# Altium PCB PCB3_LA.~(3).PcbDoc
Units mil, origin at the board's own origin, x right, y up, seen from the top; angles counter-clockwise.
Board outline 1968 x 1968 mil, 4 copper layers (Top Layer, Internal Plane 1, Internal Plane 2, Bottom Layer), stack 18.2 mil thick; 12 components, 11 nets, 38 pads, 0 vias.
Unrouted connection lines stored in the file: 24.
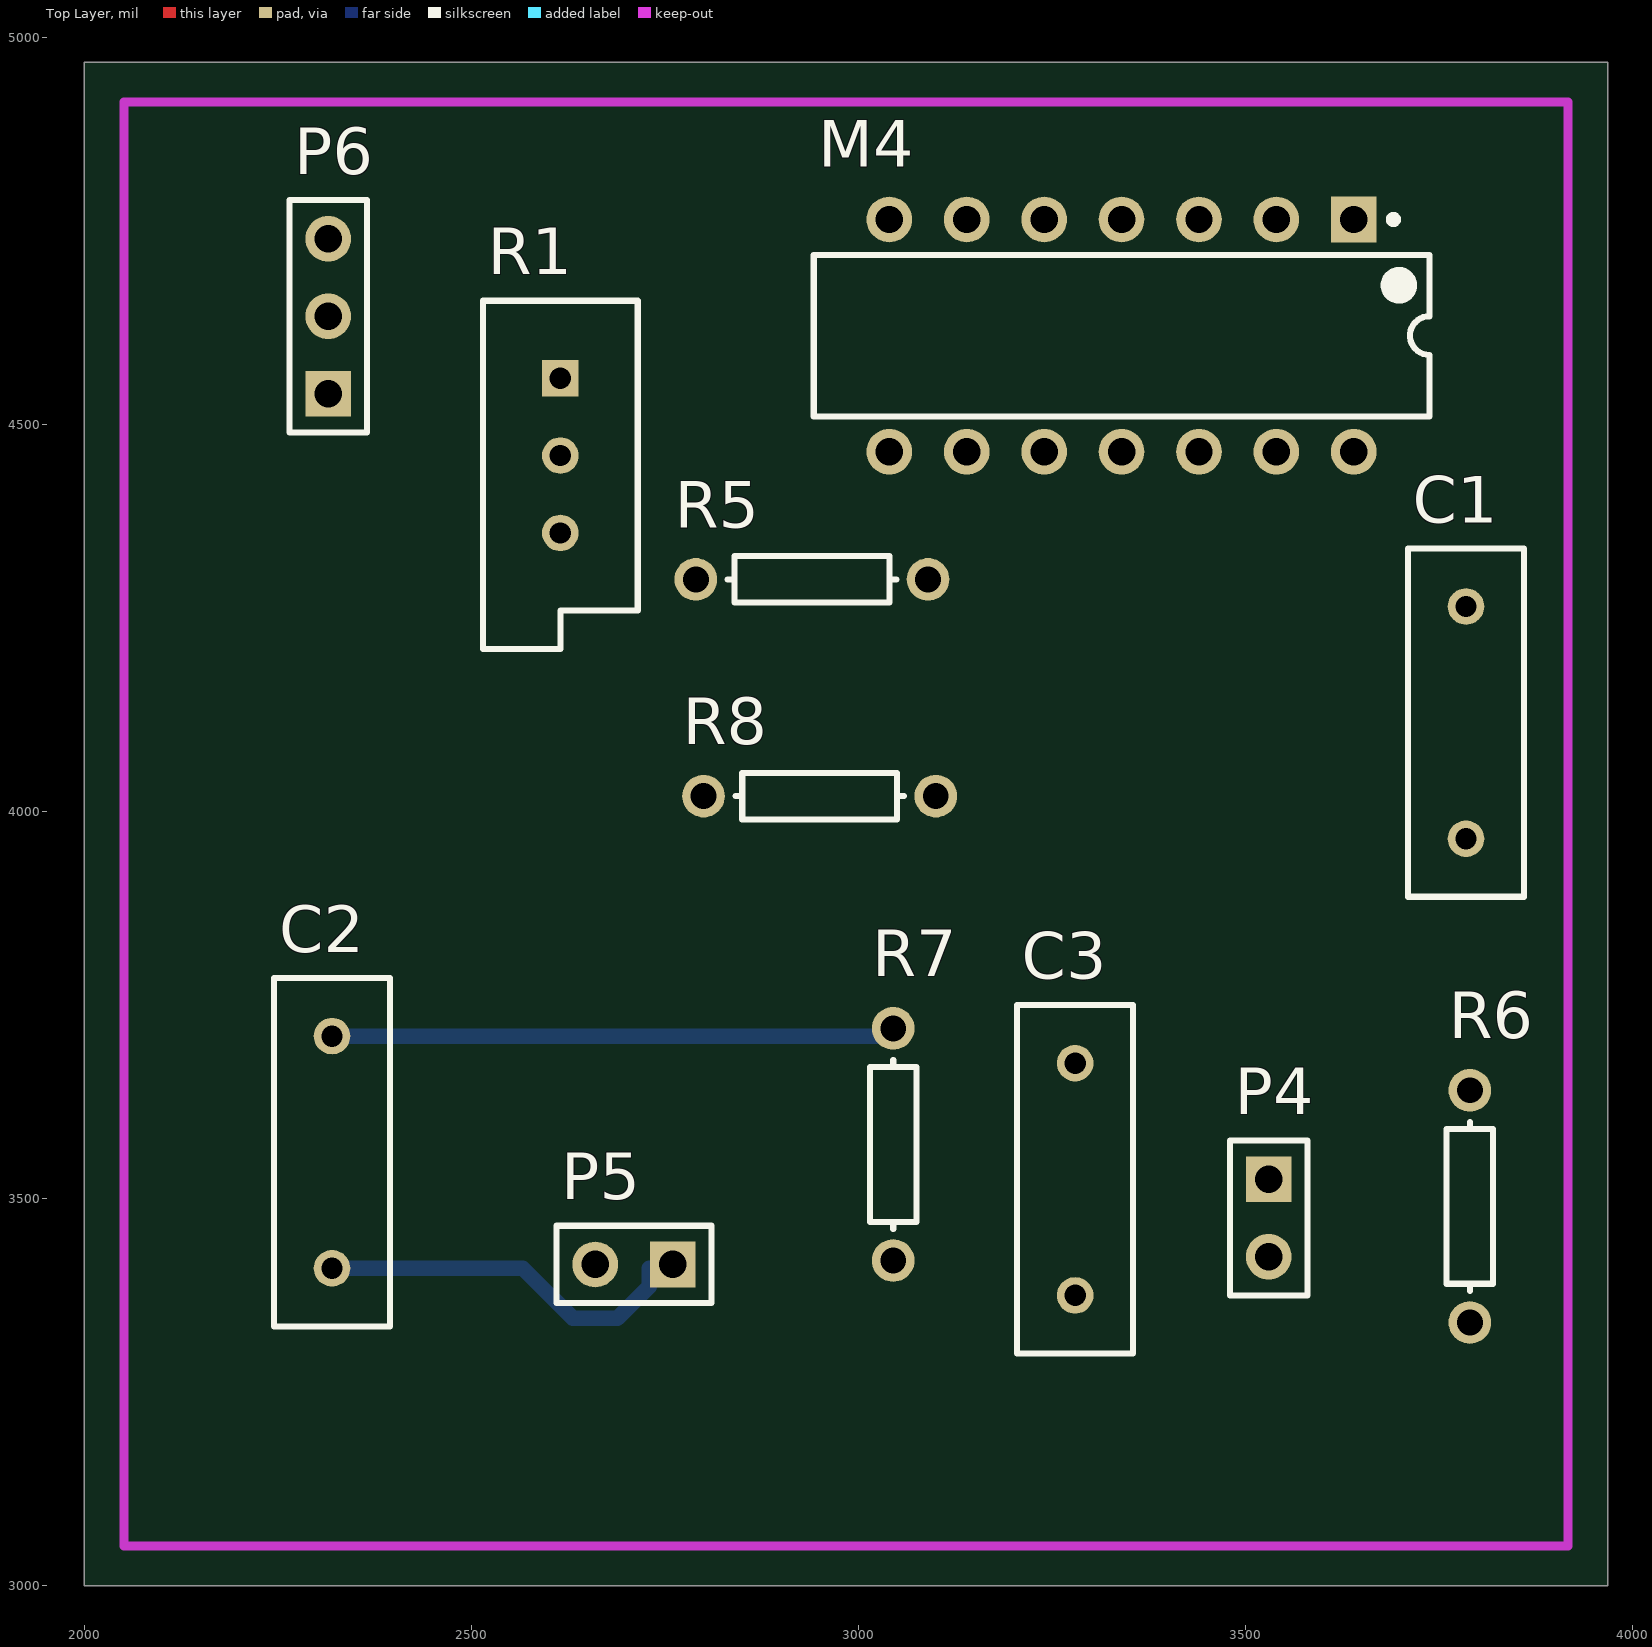
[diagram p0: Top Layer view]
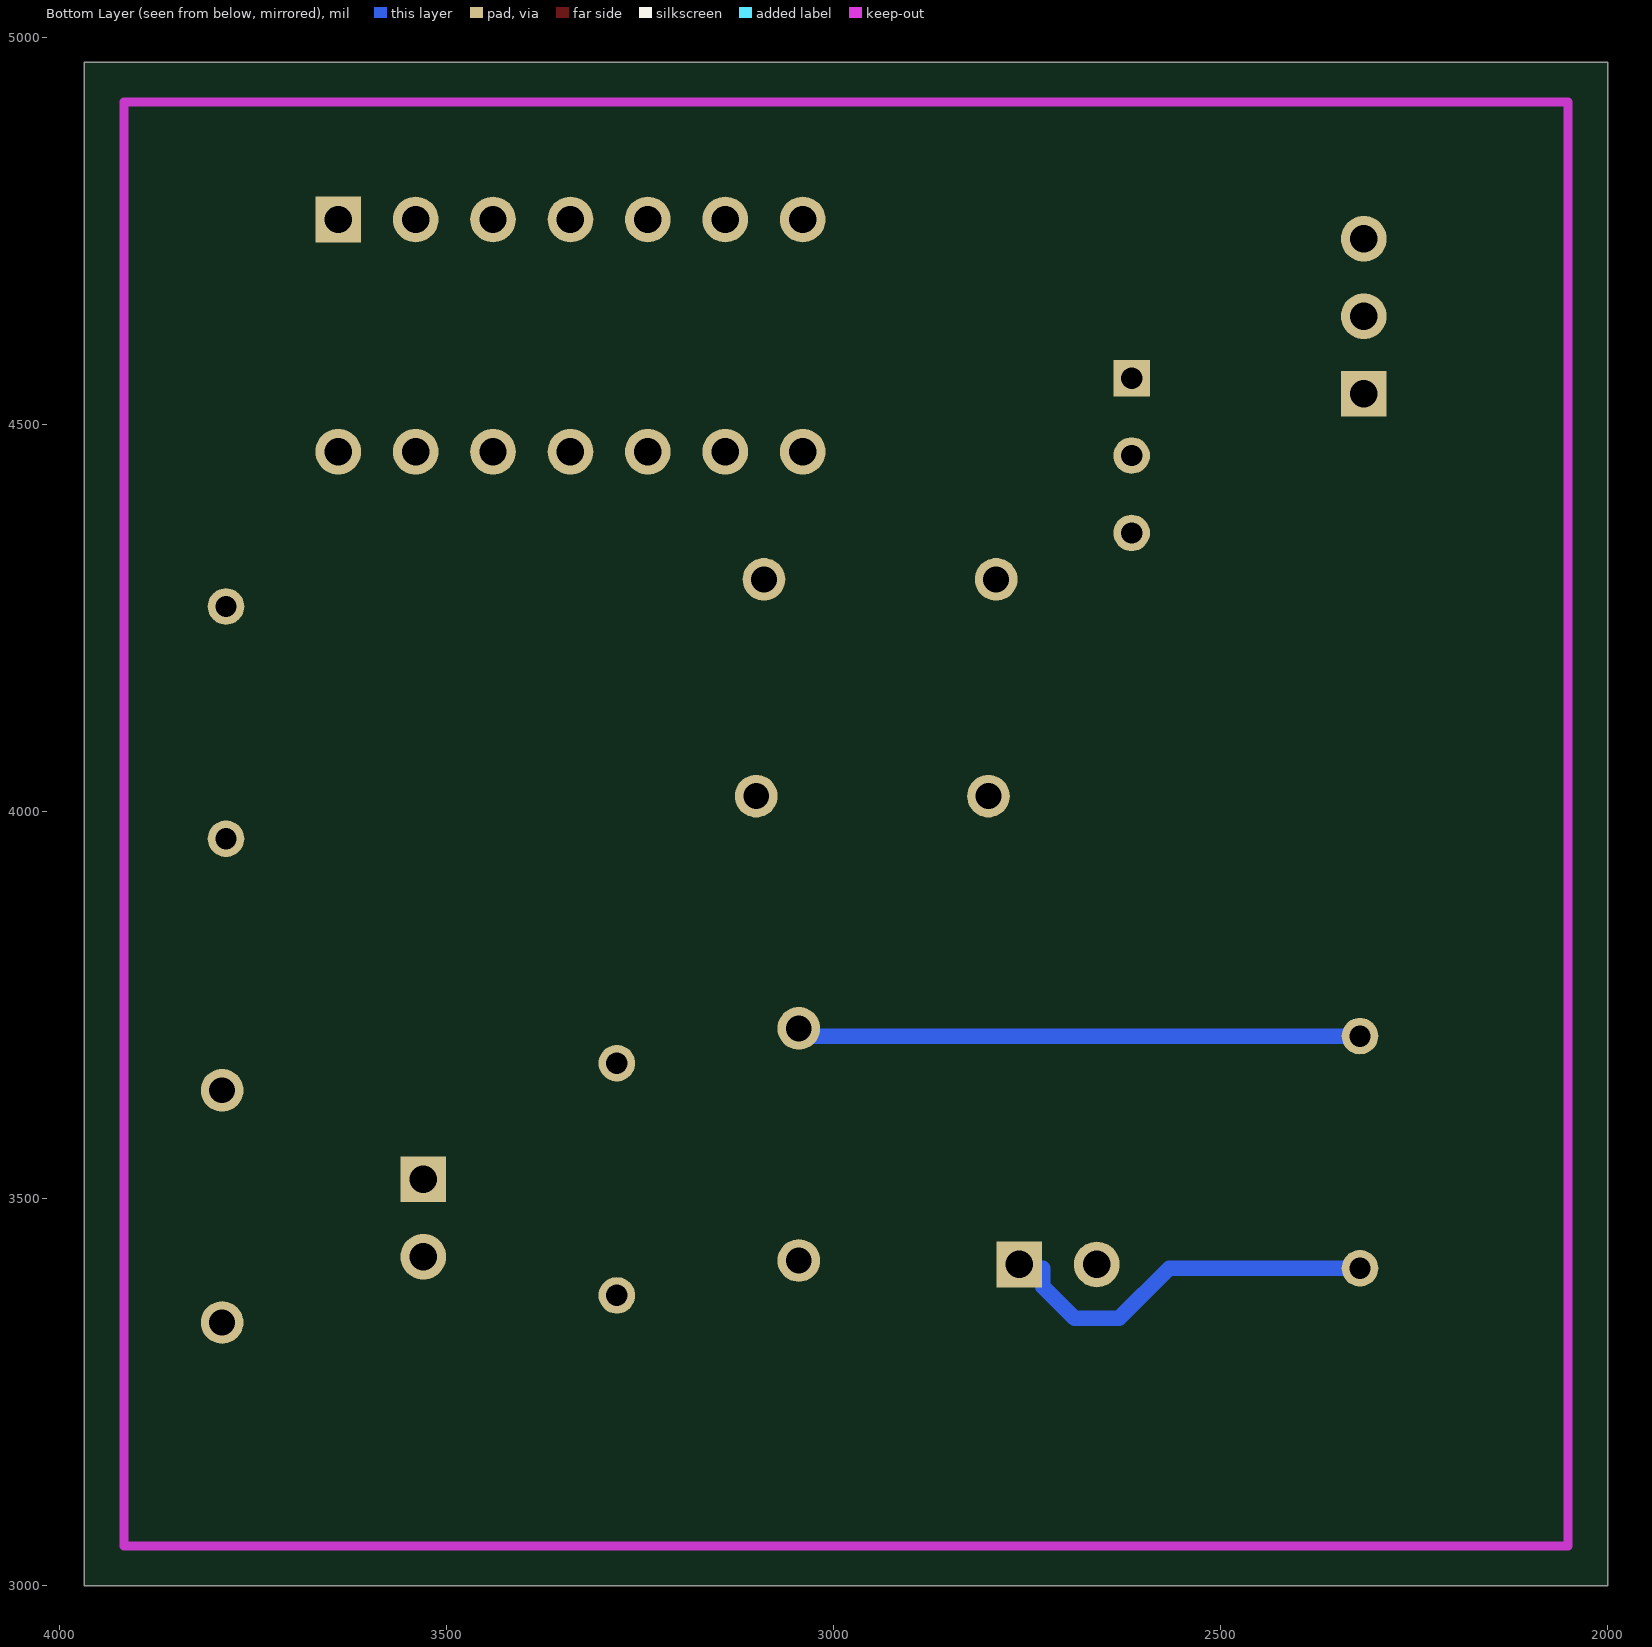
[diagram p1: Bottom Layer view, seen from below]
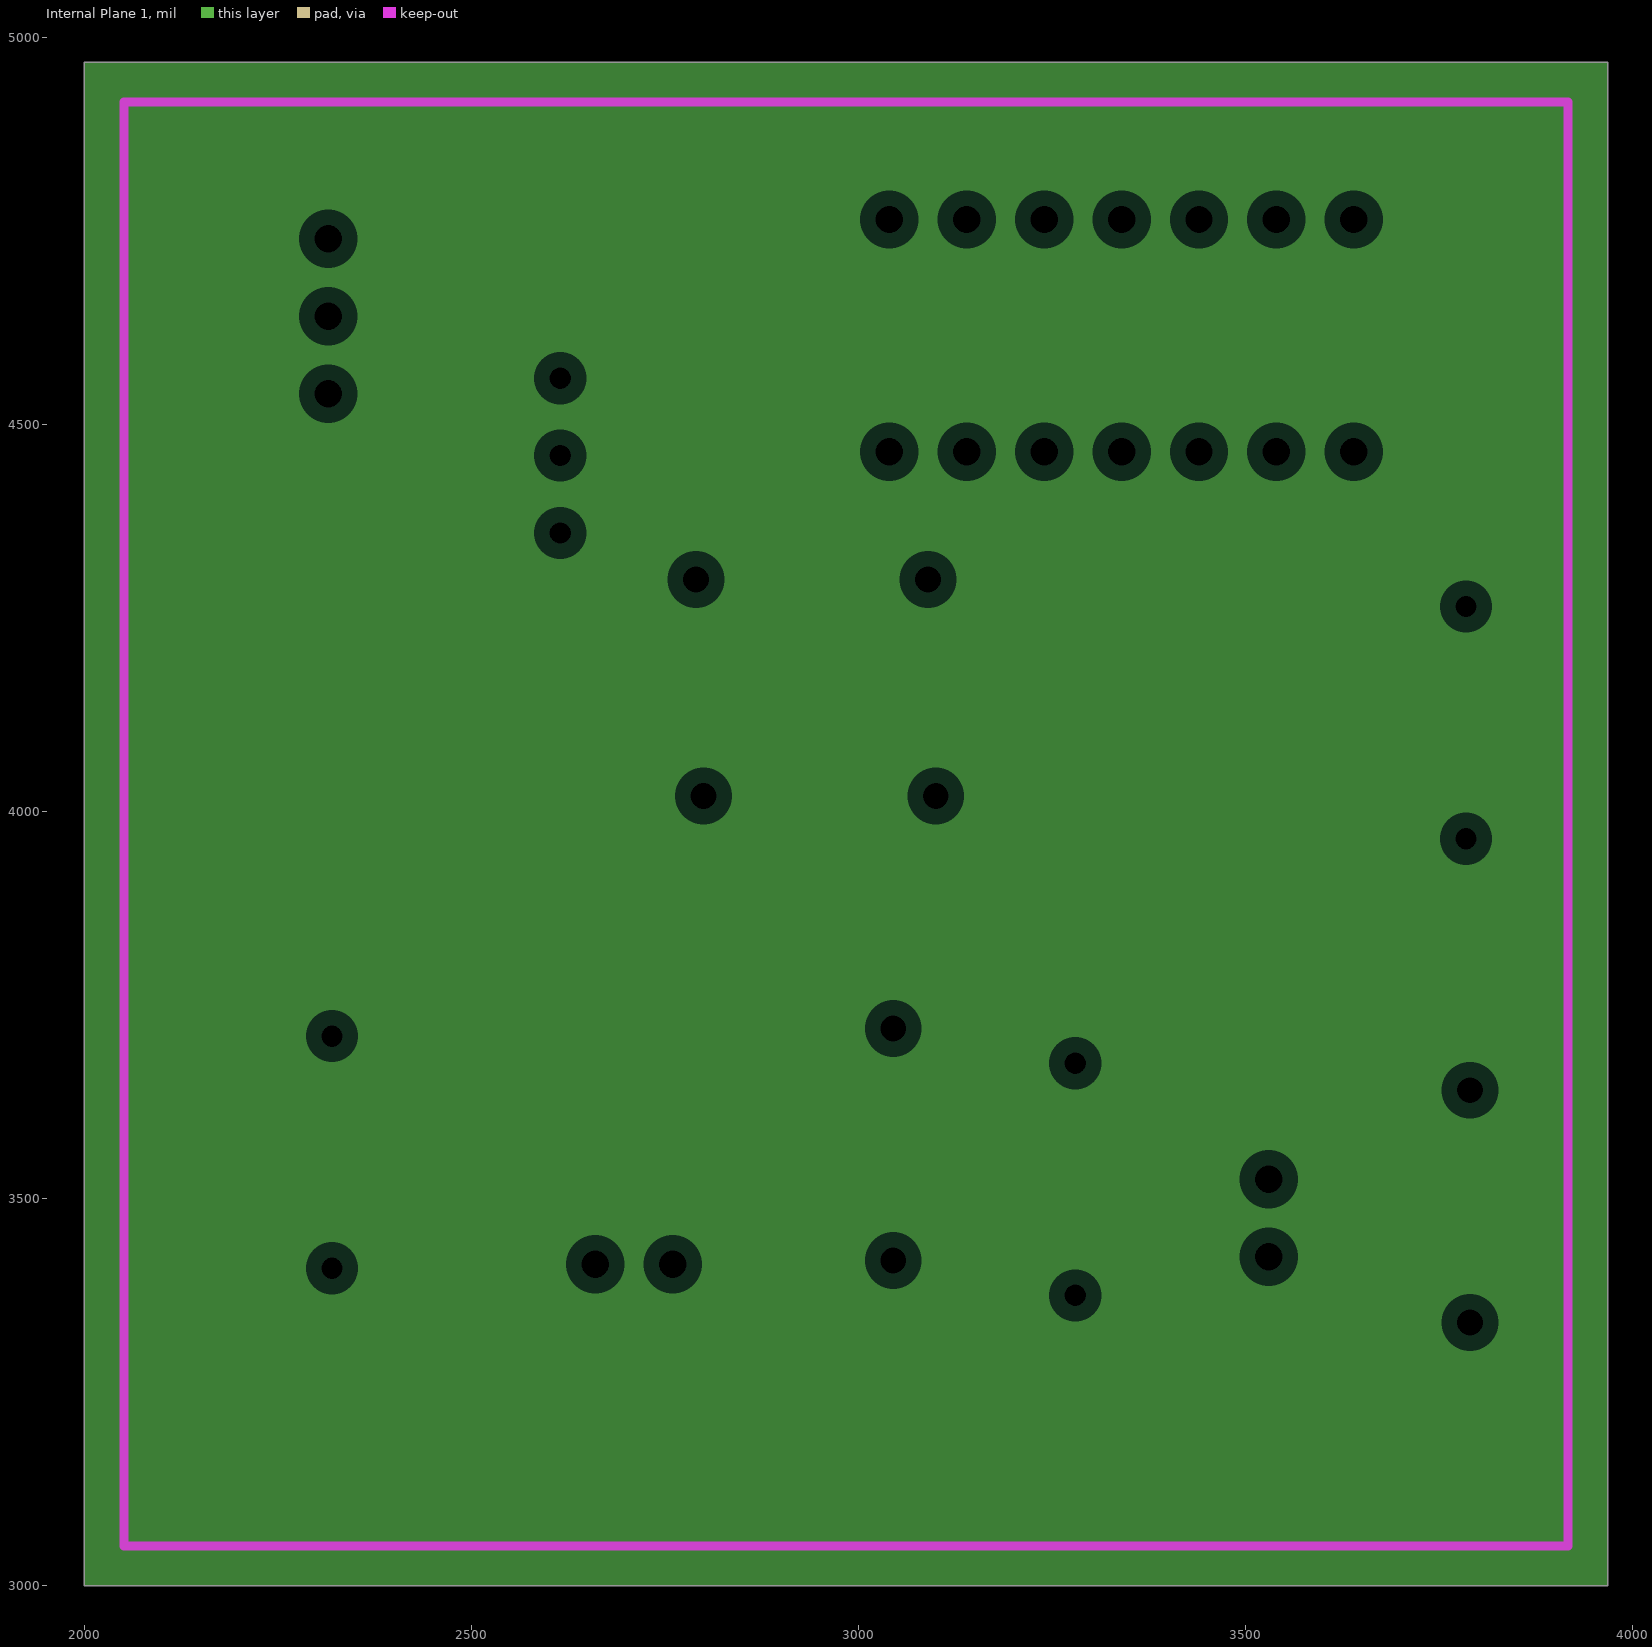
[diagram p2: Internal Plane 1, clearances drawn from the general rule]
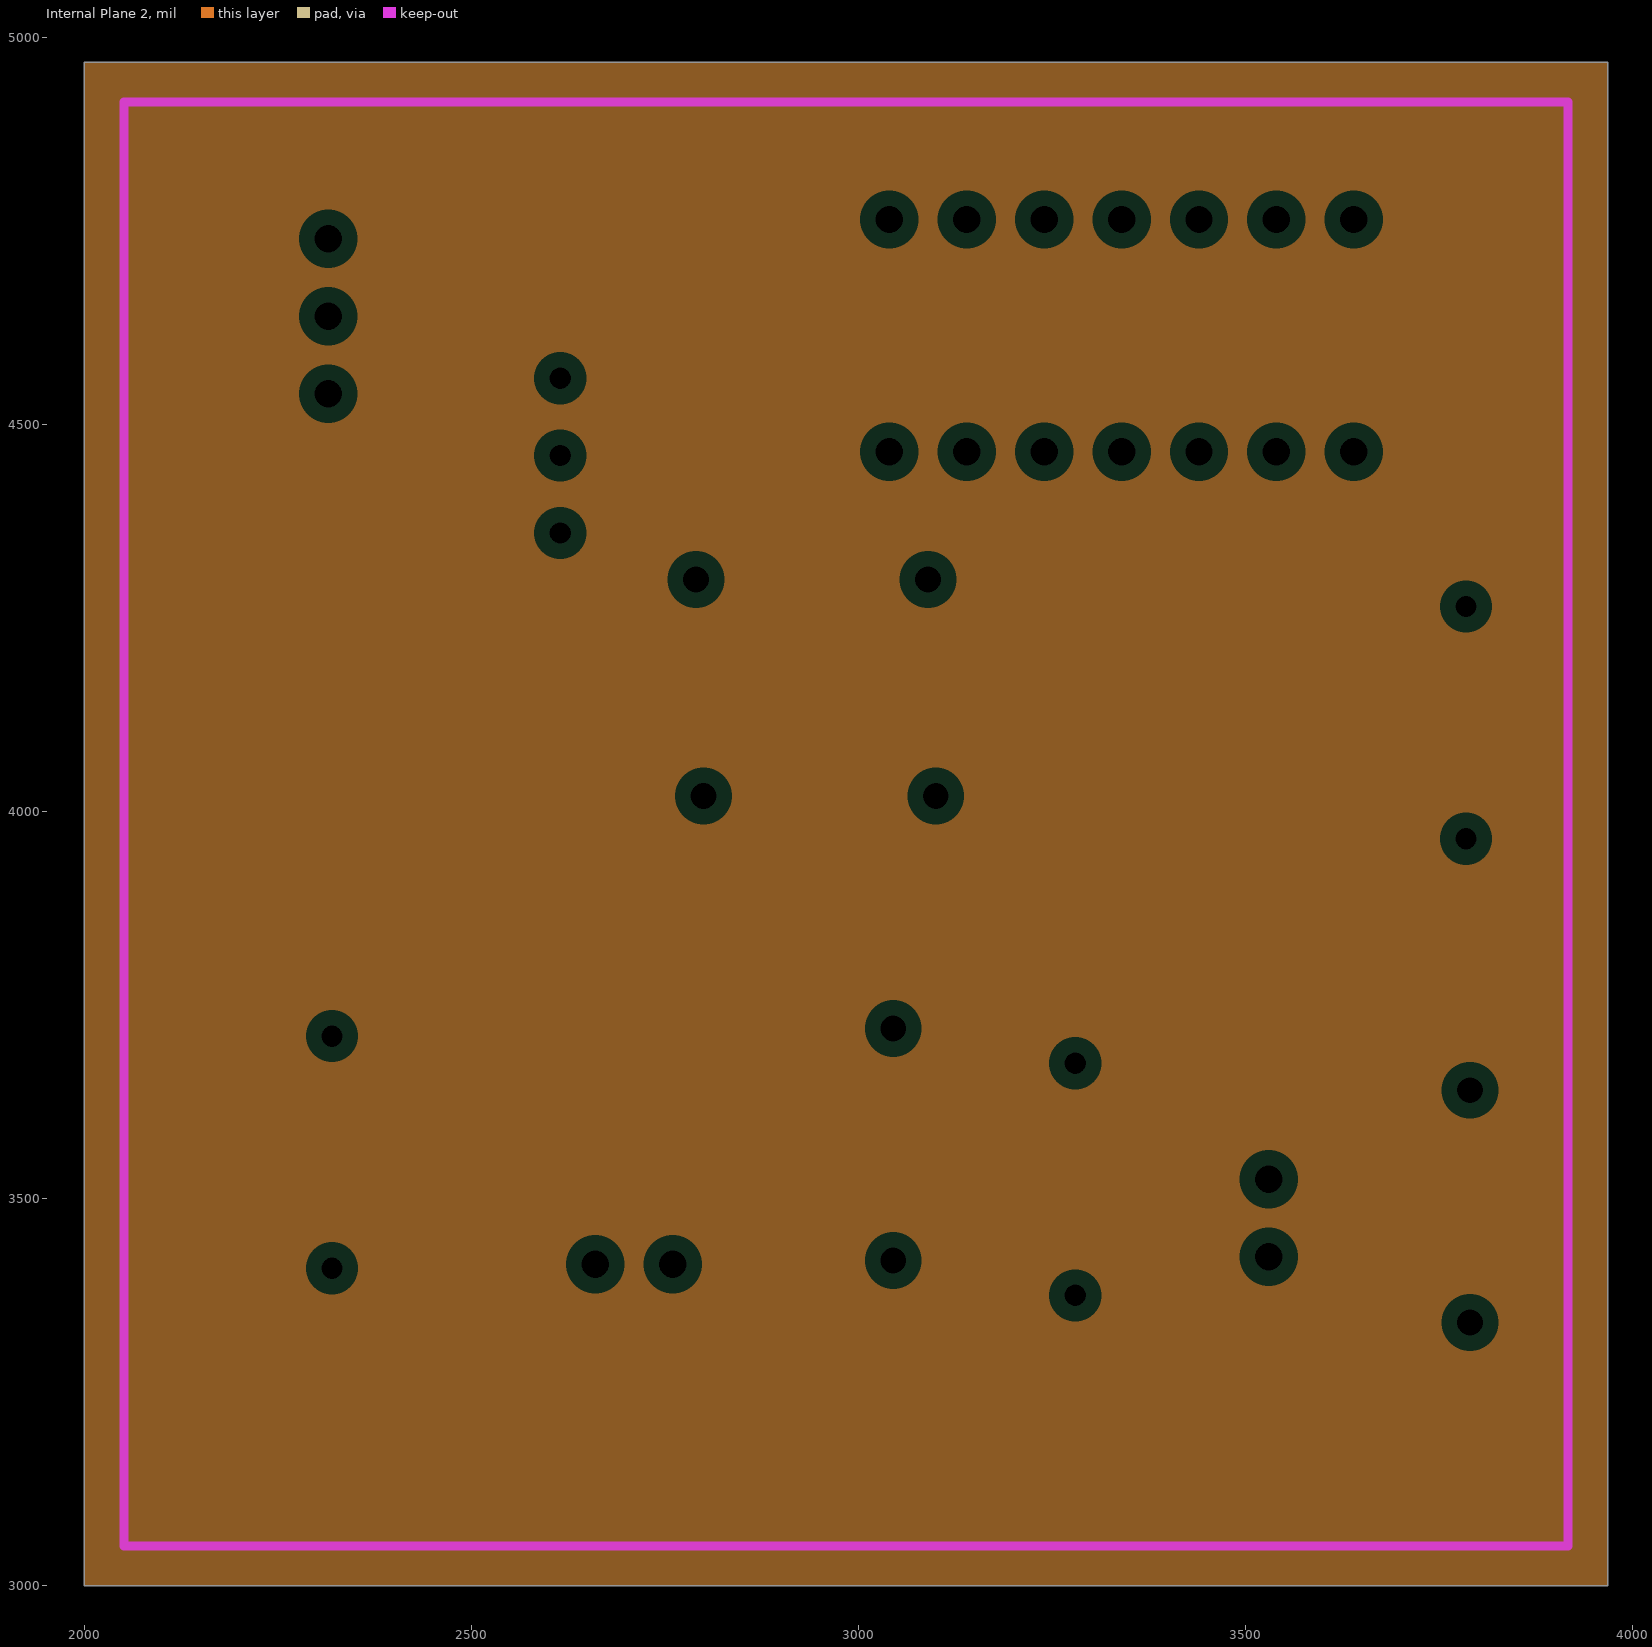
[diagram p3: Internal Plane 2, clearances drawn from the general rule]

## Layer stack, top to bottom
Top Solder: solder mask 0.4, Solder Resist, Dk 3.5
Top Layer: signal copper 1.4
Internal Plane 1: plane copper 1.4
Internal Plane 2: plane copper 1.4
Dielectric 1: dielectric 12.6, FR-4, Dk 4.8
Bottom Layer: signal copper 1.4
Bottom Solder: solder mask 0.4, Solder Resist, Dk 3.5

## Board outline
2000,3000 3968,3000 3968,4968 2000,4968

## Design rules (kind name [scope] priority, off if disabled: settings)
Clearance [All] p1: gap=30
PlaneClearance [All] p1: clearance=20
PlaneConnect [All] p1: planeconnectstyle=Relief reliefexpansion=20 reliefentries=4 reliefconductorwidth=10 reliefairgap=10
PolygonConnect [All] p1: connectstyle=Relief reliefconductorwidth=10 reliefentries=4 polygonreliefangle="90 Angle" airgapwidth=10
RoutingVias [All] p1: holewidth=32 width=62 viastyle="Through Hole" minholewidth=28 minwidth=50 maxholewidth=28 maxwidth=50
SolderMaskExpansion [All] p1: expansion=4
Width [All] p1: maxlimit=20 minlimit=20 preferedwidth=20
28 further rules are at their usual default settings.

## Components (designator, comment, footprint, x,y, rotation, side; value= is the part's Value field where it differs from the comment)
C1 "Cap" RAD-0.3 3785,4115 r90 top
C2 "Cap" RAD-0.3 2320,3560 r90 top
C3 "Cap" RAD-0.3 3280,3525 r270 top
M4 "ALD1106" DIP-14 3340,4615 r270 top
P4 "Header 2" HDR1X2 3530,3525 r270 top
P5 "Header 2" HDR1X2 2760,3415 r180 top
P6 "Header 3" HDR1X3 2315,4540 r90 top
R1 "RPot" VR5 2615,4460 r270 top
R5 "Res1" AXIAL-0.3 2940,4300 r180 top
R6 "Res1" AXIAL-0.3 3790,3490 r270 top
R7 "Res1" AXIAL-0.3 3045,3570 r270 top
R8 "Res1" AXIAL-0.3 2950,4020 r180 top

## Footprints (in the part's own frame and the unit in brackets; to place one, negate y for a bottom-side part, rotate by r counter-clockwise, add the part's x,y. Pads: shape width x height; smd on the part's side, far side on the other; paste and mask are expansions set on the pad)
AXIAL-0.3 [mm] "Axial Device, Thru-Hole; 2 Leads; 0.3 in Pin Spacing"
  round 1.4 hole 0.85: 1(-3.81,0) 2(3.81,0)
  silkscreen extent -2.77,-0.76 2.77,0.76
DIP-14 [mm] "DIP, 14-Pin, Row Spacing 7.62 mm, Pitch 2.54 mm"
  rect 1.5x1.5 hole 0.9: 1(-3.81,7.62)
  round 1.5 hole 0.9: 2(-3.81,5.08) 3(-3.81,2.54) 4(-3.81,0) 5(-3.81,-2.54) 6(-3.81,-5.08) 7(-3.81,-7.62) 8(3.81,-7.62) 9(3.81,-5.08) 10(3.81,-2.54) 11(3.81,0) 12(3.81,2.54) 13(3.81,5.08) 14(3.81,7.62)
  silkscreen extent -3.93,-10.1 2.65,10.1, body extent -3.6,-10.1 3.6,10.1, height 5.08
HDR1X2 [mm] "Connector; Header; 2 Position"
  rect 1.5x1.5 hole 0.9: 1(0,0)
  round 1.5 hole 0.9: 2(2.54,0)
  silkscreen extent -1.27,-1.27 3.81,1.27
HDR1X3 [mm] "Connector; Header; 3 Position"
  rect 1.5x1.5 hole 0.9: 1(0,0)
  round 1.5 hole 0.9: 2(2.54,0) 3(5.08,0)
  silkscreen extent -1.27,-1.27 6.35,1.27
RAD-0.3 [mm] "Radial Cap, Thru-Hole; 2 Leads; 0.3 in Pin Spacing"
  round 1.2 hole 0.7: 1(-3.81,0) 2(3.81,0)
  silkscreen extent -5.71,-1.91 5.71,1.91
VR5 [mm] "Thru-Hole; 3 Leads"
  rect 1.2x1.2 hole 0.7: 1(-2.54,0)
  round 1.2 hole 0.7: 2(0,0) 3(2.54,0)
  silkscreen extent -5.08,-2.54 6.35,2.54

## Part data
C1 C2 C3: "Capacitor"
M4: "Quad N-channel matched MOSFET array"
P4 P5: "Header, 2-Pin"
P6: "Header, 3-Pin"
R1: "Potentiometer"
R5 R6 R7 R8: "Resistor"

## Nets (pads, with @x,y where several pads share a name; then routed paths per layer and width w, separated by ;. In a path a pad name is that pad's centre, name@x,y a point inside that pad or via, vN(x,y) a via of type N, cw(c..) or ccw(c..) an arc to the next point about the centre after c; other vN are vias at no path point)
GND: C3.2 P4.2 P5.2 P6.2 R6.2 R7.2
NetC1_1: C1.1 P4.1 R6.1
NetC1_2: C1.2 M4.14 R5.1
NetC2_1: C2.1 P5.1 | length 502.4
  Bottom Layer w20: C2.1 2566.67,3410 2631.2,3345.47 2688.8,3345.47 2729.53,3386.2 2729.53,3410 P5.1@2755,3410
NetC2_2: C2.2 M4.13 R7.1 | length 715
  Bottom Layer w20: C2.2 R7.1@3035,3710
NetC3_1: C3.1 M4.5 M4.12
NetM4_6: M4.6 M4.9
NetM4_10: M4.10 R8.1
NetR1_2: R1.2 R1.3 R8.2
VDD: P6.1 R1.1 R5.2
VSS: M4.1 M4.2 M4.3 M4.4 M4.7 M4.8 P6.3
pads on no net: M4.11

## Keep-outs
Keep-Out Layer:
  lines w11.81: 2051.18,3051.18 2051.18,4916.82 3916.82,4916.82 3916.82,3051.18 2051.18,3051.18

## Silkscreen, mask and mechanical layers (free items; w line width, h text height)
Drill Drawing:
  text ".LEGEND" at 4168,3200 h60
  text "Drill Drawing." at 4168,3100 h60

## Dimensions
2051.18,3051.18 to 2051.18,4916.82 on Mechanical 1
2051.18,3051.18 to 3916.82,3051.18 on Mechanical 1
